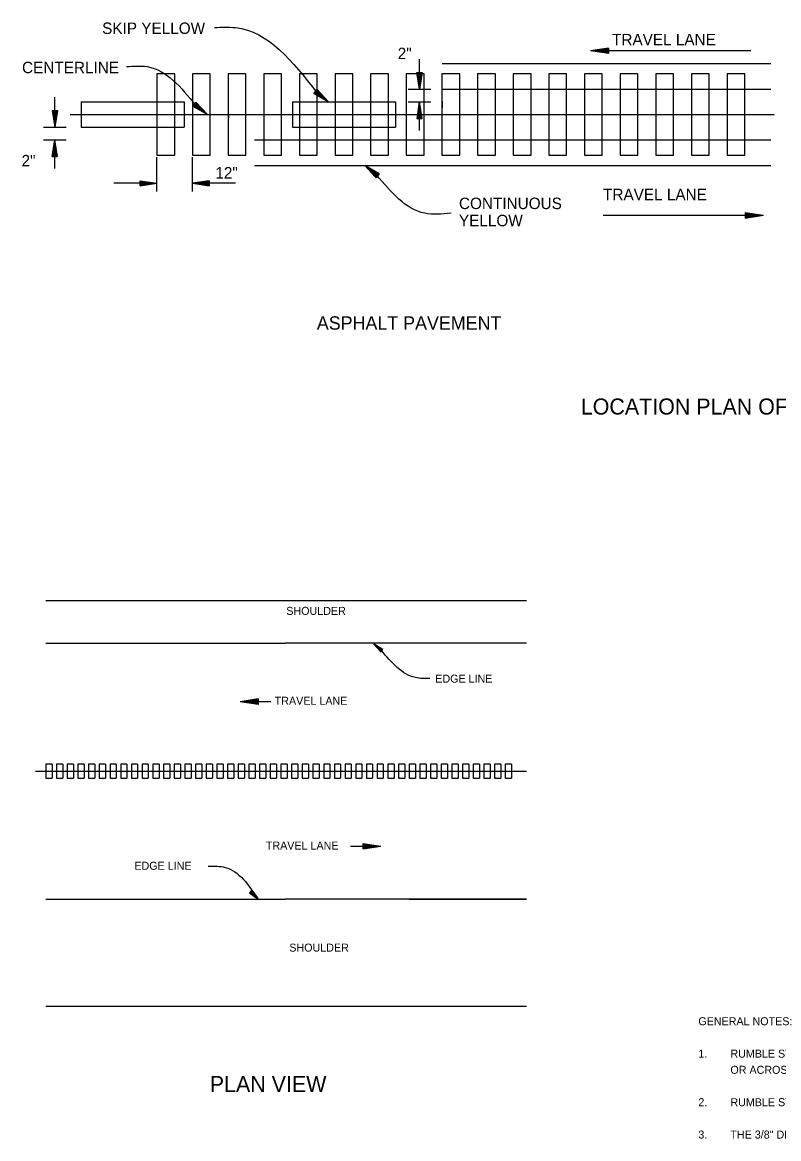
# Model space of a CAD drawing. Extents: x 28704 to 32542, y 50360 to 59122.
# Drawn here: x 31087 to 31666, y 50408 to 51264 of the extents above; entities that cross this region are included whole.
import ezdxf

# ---------------------------------------------------------------- set-up
doc = ezdxf.new("R2010")
doc.units = 0
doc.layers.add('Default', color=7, linetype='Continuous')
doc.layers.add('R_Alt Surface', color=7, linetype='Continuous')

msp = doc.modelspace()

# ---------------------------------------------------------------- linework, layer by layer
at = {"layer": 'Default'}
for p, q in [((31535.97, 51243.94), (31522, 51241.84)), ((31644.8, 51241.84), (31522, 51241.84)), ((31535.97, 51239.75), (31522, 51241.84)), ((31535.97, 51243.59), (31524.34, 51241.84)), ((31535.97, 51240.1), (31524.34, 51241.84)), ((31535.97, 51243.23), (31526.74, 51241.84)), ((31535.97, 51240.45), (31526.74, 51241.84)), ((31535.97, 51242.88), (31529.06, 51241.84)), ((31535.97, 51240.8), (31529.06, 51241.84)), ((31535.97, 51242.52), (31531.43, 51241.84)), ((31535.97, 51241.16), (31531.43, 51241.84)), ((31535.97, 51242.17), (31533.76, 51241.84)), ((31535.97, 51241.52), (31533.76, 51241.84)), ((31535.97, 51243.94), (31535.97, 51239.75)), ((31390.99, 51212.52), (31390.99, 51235.58)), ((31389.13, 51225.33), (31391.05, 51212.52)), ((31389.13, 51225.33), (31392.97, 51225.33)), ((31389.45, 51225.33), (31391.05, 51214.66)), ((31389.77, 51225.33), (31391.05, 51216.86)), ((31390.09, 51225.33), (31391.05, 51218.99)), ((31390.43, 51225.33), (31391.05, 51221.16)), ((31390.75, 51225.33), (31391.05, 51223.3)), ((31392.97, 51225.33), (31391.05, 51212.52)), ((31391.68, 51225.33), (31391.05, 51221.16)), ((31392.32, 51225.33), (31391.05, 51216.86)), ((31392.65, 51225.33), (31391.05, 51214.66)), ((31392, 51225.33), (31391.05, 51218.99)), ((31391.35, 51225.33), (31391.05, 51223.3)), ((31111.49, 51183.26), (31111.49, 51206.32)), ((31310.09, 51209.25), (31312.48, 51212.26)), ((31310.09, 51209.25), (31321.3, 51202.77)), ((31310.29, 51209.5), (31319.62, 51204.1)), ((31310.49, 51209.76), (31317.9, 51205.47)), ((31310.69, 51210.01), (31316.24, 51206.8)), ((31310.9, 51210.27), (31314.54, 51208.16)), ((31311.1, 51210.52), (31312.87, 51209.49)), ((31311.47, 51210.99), (31312.87, 51209.49)), ((31311.68, 51211.25), (31314.54, 51208.16)), ((31311.88, 51211.5), (31316.24, 51206.8)), ((31312.08, 51211.75), (31317.9, 51205.47)), ((31312.28, 51212.01), (31319.62, 51204.1)), ((31312.48, 51212.26), (31321.3, 51202.77)), ((31382.3, 51212.52), (31399.8, 51212.52)), ((31109.63, 51196.07), (31111.55, 51183.26)), ((31109.63, 51196.07), (31113.47, 51196.07)), ((31109.95, 51196.07), (31111.55, 51185.4)), ((31110.28, 51196.07), (31111.55, 51187.6)), ((31110.6, 51196.07), (31111.55, 51189.74)), ((31110.93, 51196.07), (31111.55, 51191.9)), ((31111.25, 51196.07), (31111.55, 51194.04)), ((31113.47, 51196.07), (31111.55, 51183.26)), ((31112.18, 51196.07), (31111.55, 51191.9)), ((31112.83, 51196.07), (31111.55, 51187.6)), ((31113.15, 51196.07), (31111.55, 51185.4)), ((31112.5, 51196.07), (31111.55, 51189.74)), ((31111.85, 51196.07), (31111.55, 51194.04)), ((31217.24, 51199.5), (31219.64, 51202.5)), ((31217.24, 51199.5), (31228.45, 51193.02)), ((31217.44, 51199.75), (31226.78, 51194.35)), ((31217.64, 51200), (31225.06, 51195.72)), ((31217.84, 51200.26), (31223.39, 51197.05)), ((31218.05, 51200.52), (31221.69, 51198.4)), ((31218.25, 51200.77), (31220.02, 51199.74)), ((31218.63, 51201.24), (31220.02, 51199.74)), ((31218.83, 51201.49), (31221.69, 51198.4)), ((31219.03, 51201.75), (31223.39, 51197.05)), ((31219.23, 51202), (31225.06, 51195.72)), ((31219.44, 51202.25), (31226.78, 51194.35)), ((31219.64, 51202.5), (31228.45, 51193.02)), ((31382.3, 51202.77), (31399.8, 51202.77)), ((31389.13, 51189.96), (31391.05, 51202.77)), ((31389.45, 51189.96), (31391.05, 51200.63)), ((31389.78, 51189.96), (31391.05, 51198.43)), ((31390.1, 51189.96), (31391.05, 51196.3)), ((31392.97, 51189.96), (31391.05, 51202.77)), ((31392.65, 51189.96), (31391.05, 51200.63)), ((31392.32, 51189.96), (31391.05, 51198.43)), ((31392, 51189.96), (31391.05, 51196.3)), ((31123.41, 51193.02), (31662.88, 51193.02)), ((31392.97, 51189.96), (31389.13, 51189.96)), ((31390.42, 51189.96), (31391.05, 51194.13)), ((31390.75, 51189.96), (31391.05, 51191.99)), ((31390.99, 51180.83), (31390.99, 51189.96)), ((31391.67, 51189.96), (31391.05, 51194.13)), ((31391.35, 51189.96), (31391.05, 51191.99)), ((31102.8, 51183.26), (31120.3, 51183.26)), ((31102.8, 51173.51), (31120.3, 51173.51)), ((31109.63, 51160.7), (31111.55, 51173.51)), ((31109.95, 51160.7), (31111.55, 51171.37)), ((31113.47, 51160.7), (31111.55, 51173.51)), ((31113.15, 51160.7), (31111.55, 51171.37)), ((31110.28, 51160.7), (31111.55, 51169.17)), ((31110.6, 51160.7), (31111.55, 51167.04)), ((31110.92, 51160.7), (31111.55, 51164.87)), ((31111.25, 51160.7), (31111.55, 51162.73)), ((31112.83, 51160.7), (31111.55, 51169.17)), ((31112.51, 51160.7), (31111.55, 51167.04)), ((31112.17, 51160.7), (31111.55, 51164.87)), ((31111.85, 51160.7), (31111.55, 51162.73)), ((31113.47, 51160.7), (31109.63, 51160.7)), ((31111.49, 51151.57), (31111.49, 51160.7)), ((31189.74, 51133.93), (31189.74, 51160.2)), ((31216.99, 51133.89), (31216.99, 51160.26)), ((31360.2, 51147.5), (31349, 51154)), ((31357.8, 51144.5), (31349, 51154)), ((31360, 51147.25), (31350.67, 51152.67)), ((31358, 51144.75), (31350.67, 51152.67)), ((31358.2, 51145.01), (31352.39, 51151.29)), ((31359.8, 51147), (31352.39, 51151.29)), ((31359.6, 51146.75), (31354.06, 51149.96)), ((31358.41, 51145.26), (31354.06, 51149.96)), ((31358.61, 51145.51), (31355.75, 51148.6)), ((31359.39, 51146.49), (31355.75, 51148.6)), ((31358.81, 51145.77), (31357.42, 51147.27)), ((31359.19, 51146.24), (31357.42, 51147.27)), ((31360.2, 51147.5), (31357.8, 51144.5)), ((31176.93, 51140.32), (31156.84, 51140.32)), ((31176.92, 51142.24), (31189.74, 51140.38)), ((31176.94, 51138.4), (31176.92, 51142.24)), ((31176.93, 51141.92), (31187.6, 51140.37)), ((31176.93, 51141.59), (31185.4, 51140.36)), ((31176.93, 51141.27), (31183.27, 51140.35)), ((31176.93, 51140.95), (31181.1, 51140.34)), ((31176.93, 51140.62), (31178.96, 51140.33)), ((31176.93, 51140.02), (31178.96, 51140.33)), ((31176.94, 51138.4), (31189.74, 51140.38)), ((31176.94, 51138.72), (31187.6, 51140.37)), ((31176.94, 51139.05), (31185.4, 51140.36)), ((31176.94, 51139.37), (31183.27, 51140.35)), ((31176.94, 51139.7), (31181.1, 51140.34)), ((31229.81, 51142.21), (31216.99, 51140.34)), ((31229.79, 51138.37), (31216.99, 51140.34)), ((31229.8, 51141.89), (31219.13, 51140.33)), ((31229.79, 51138.69), (31219.13, 51140.33)), ((31229.8, 51141.56), (31221.33, 51140.32)), ((31229.79, 51139.01), (31221.33, 51140.32)), ((31229.8, 51141.24), (31223.46, 51140.32)), ((31229.79, 51139.33), (31223.46, 51140.32)), ((31229.8, 51140.91), (31225.63, 51140.31)), ((31229.79, 51139.66), (31225.63, 51140.31)), ((31229.8, 51140.59), (31227.77, 51140.3)), ((31229.8, 51139.99), (31227.77, 51140.3)), ((31229.81, 51142.21), (31229.79, 51138.37)), ((31249.89, 51140.29), (31229.8, 51140.29)), ((31531.78, 51115.7), (31654.58, 51115.7)), ((31640.61, 51117.79), (31654.58, 51115.7)), ((31640.61, 51117.79), (31640.61, 51113.6)), ((31640.61, 51117.44), (31652.25, 51115.7)), ((31640.61, 51117.09), (31649.85, 51115.7)), ((31640.61, 51116.74), (31647.52, 51115.7)), ((31640.61, 51116.37), (31645.15, 51115.7)), ((31640.61, 51116.02), (31642.82, 51115.7)), ((31640.61, 51113.6), (31654.58, 51115.7)), ((31640.61, 51115.01), (31645.15, 51115.7)), ((31640.61, 51114.31), (31649.85, 51115.7)), ((31640.61, 51113.95), (31652.25, 51115.7)), ((31640.61, 51114.66), (31647.52, 51115.7)), ((31640.61, 51115.37), (31642.82, 51115.7))]:
    msp.add_line(p, q, dxfattribs=at)
for points in [[(31189.74, 51224.21), (31189.74, 51161.82), (31203.39, 51161.82), (31203.39, 51224.21)], [(31217.05, 51224.21), (31217.05, 51161.82), (31230.7, 51161.82), (31230.7, 51224.21)], [(31244.35, 51224.21), (31244.35, 51161.82), (31258.01, 51161.82), (31258.01, 51224.21)], [(31271.66, 51224.21), (31271.66, 51161.82), (31285.31, 51161.82), (31285.31, 51224.21)], [(31298.97, 51224.21), (31298.97, 51161.82), (31312.62, 51161.82), (31312.62, 51224.21)], [(31326.28, 51224.21), (31326.28, 51161.82), (31339.93, 51161.82), (31339.93, 51224.21)], [(31353.58, 51224.21), (31353.58, 51161.82), (31367.24, 51161.82), (31367.24, 51224.21)], [(31380.89, 51224.21), (31380.89, 51161.82), (31394.54, 51161.82), (31394.54, 51224.21)], [(31408.2, 51224.21), (31408.2, 51161.82), (31421.85, 51161.82), (31421.85, 51224.21)], [(31435.51, 51224.21), (31435.51, 51161.82), (31449.16, 51161.82), (31449.16, 51224.21)], [(31462.81, 51224.21), (31462.81, 51161.82), (31476.47, 51161.82), (31476.47, 51224.21)], [(31490.12, 51224.21), (31490.12, 51161.82), (31503.77, 51161.82), (31503.77, 51224.21)], [(31517.43, 51224.21), (31517.43, 51161.82), (31531.08, 51161.82), (31531.08, 51224.21)], [(31544.73, 51224.21), (31544.73, 51161.82), (31558.39, 51161.82), (31558.39, 51224.21)], [(31572.04, 51224.21), (31572.04, 51161.82), (31585.7, 51161.82), (31585.7, 51224.21)], [(31599.35, 51224.21), (31599.35, 51161.82), (31613, 51161.82), (31613, 51224.21)], [(31626.66, 51224.21), (31626.66, 51161.82), (31640.31, 51161.82), (31640.31, 51224.21)]]:
    msp.add_lwpolyline(points, close=True, dxfattribs=at)
for points in [[(31233.81, 51259.69), (31249.89, 51259.69), (31312.16, 51210.08)], [(31166.5, 51229.74), (31182.39, 51229.74), (31219.31, 51200.32)], [(31415.17, 51117.28), (31395.06, 51117.28), (31358.14, 51146.69)]]:
    msp.add_spline(points, degree=3, dxfattribs=at)
at = {"layer": 'R_Alt Surface'}
for p, q in [((31408.33, 51232.03), (31660.31, 51232.03)), ((31408.33, 51212.52), (31660.31, 51212.52)), ((31131.85, 51202.77), (31131.85, 51183.26)), ((31131.85, 51202.77), (31210.62, 51202.77)), ((31210.62, 51202.77), (31210.62, 51183.26)), ((31293.78, 51202.77), (31293.78, 51183.26)), ((31293.78, 51202.77), (31372.56, 51202.77)), ((31372.56, 51202.77), (31372.56, 51183.26)), ((31408.33, 51203.25), (31408.33, 51198.13)), ((31244.65, 51193.02), (31244.65, 51190.46)), ((31131.85, 51183.26), (31210.62, 51183.26)), ((31293.78, 51183.26), (31372.56, 51183.26)), ((31264.63, 51173.51), (31660.31, 51173.51)), ((31264.63, 51154), (31660.31, 51154)), ((31104.72, 50820.36), (31472.99, 50820.36)), ((31104.72, 50787.62), (31287.99, 50787.62)), ((31472.99, 50787.62), (31287.99, 50787.62)), ((31361.39, 50780.91), (31355.76, 50786.98)), ((31362.92, 50782.83), (31355.76, 50786.98)), ((31361.51, 50781.07), (31356.82, 50786.13)), ((31362.8, 50782.67), (31356.82, 50786.13)), ((31362.65, 50782.5), (31357.93, 50785.27)), ((31361.65, 50781.23), (31357.93, 50785.27)), ((31361.77, 50781.4), (31358.99, 50784.41)), ((31362.53, 50782.34), (31358.99, 50784.41)), ((31362.39, 50782.18), (31360.08, 50783.53)), ((31361.9, 50781.56), (31360.08, 50783.53)), ((31362.27, 50782.01), (31361.14, 50782.69)), ((31362.02, 50781.73), (31361.14, 50782.69)), ((31361.39, 50780.91), (31362.92, 50782.83)), ((31267.45, 50744.78), (31253.69, 50742.71)), ((31277.11, 50742.71), (31253.69, 50742.71)), ((31267.45, 50740.67), (31253.69, 50742.71)), ((31267.45, 50744.43), (31255.99, 50742.71)), ((31267.45, 50741), (31255.99, 50742.71)), ((31267.45, 50744.11), (31258.34, 50742.71)), ((31267.45, 50741.36), (31258.34, 50742.71)), ((31267.45, 50743.74), (31260.61, 50742.71)), ((31267.45, 50741.69), (31260.61, 50742.71)), ((31267.45, 50743.37), (31262.97, 50742.71)), ((31267.45, 50742.04), (31262.97, 50742.71)), ((31267.45, 50743.06), (31265.26, 50742.71)), ((31267.45, 50742.39), (31265.26, 50742.71)), ((31267.45, 50744.78), (31267.45, 50740.67)), ((31109.51, 50694.83), (31104.72, 50694.83)), ((31104.72, 50694.83), (31104.72, 50683.94)), ((31109.51, 50694.83), (31109.51, 50683.94)), ((31117.7, 50694.83), (31112.91, 50694.83)), ((31112.91, 50694.83), (31112.91, 50683.94)), ((31117.7, 50694.83), (31117.7, 50683.94)), ((31125.88, 50694.83), (31121.1, 50694.83)), ((31121.1, 50694.83), (31121.1, 50683.94)), ((31125.88, 50694.83), (31125.88, 50683.94)), ((31134.07, 50694.83), (31129.28, 50694.83)), ((31129.28, 50694.83), (31129.28, 50683.94)), ((31134.07, 50694.83), (31134.07, 50683.94)), ((31142.26, 50694.83), (31137.47, 50694.83)), ((31137.47, 50694.83), (31137.47, 50683.94)), ((31142.26, 50694.83), (31142.26, 50683.94)), ((31150.44, 50694.83), (31145.65, 50694.83)), ((31145.65, 50694.83), (31145.65, 50683.94)), ((31150.44, 50694.83), (31150.44, 50683.94)), ((31158.63, 50694.83), (31153.84, 50694.83)), ((31153.84, 50694.83), (31153.84, 50683.94)), ((31158.63, 50694.83), (31158.63, 50683.94)), ((31166.82, 50694.83), (31162.03, 50694.83)), ((31162.03, 50694.83), (31162.03, 50683.94)), ((31166.82, 50694.83), (31166.82, 50683.94)), ((31175, 50694.83), (31170.21, 50694.83)), ((31170.21, 50694.83), (31170.21, 50683.94)), ((31175, 50694.83), (31175, 50683.94)), ((31183.19, 50694.83), (31178.4, 50694.83)), ((31178.4, 50694.83), (31178.4, 50683.94)), ((31183.19, 50694.83), (31183.19, 50683.94)), ((31191.38, 50694.83), (31186.59, 50694.83)), ((31186.59, 50694.83), (31186.59, 50683.94)), ((31191.38, 50694.83), (31191.38, 50683.94)), ((31199.56, 50694.83), (31194.77, 50694.83)), ((31194.77, 50694.83), (31194.77, 50683.94)), ((31199.56, 50694.83), (31199.56, 50683.94)), ((31207.75, 50694.83), (31202.96, 50694.83)), ((31202.96, 50694.83), (31202.96, 50683.94)), ((31207.75, 50694.83), (31207.75, 50683.94)), ((31215.93, 50694.83), (31211.15, 50694.83)), ((31211.15, 50694.83), (31211.15, 50683.94)), ((31215.93, 50694.83), (31215.93, 50683.94)), ((31224.12, 50694.83), (31219.33, 50694.83)), ((31219.33, 50694.83), (31219.33, 50683.94)), ((31224.12, 50694.83), (31224.12, 50683.94)), ((31232.31, 50694.83), (31227.52, 50694.83)), ((31227.52, 50694.83), (31227.52, 50683.94)), ((31232.31, 50694.83), (31232.31, 50683.94)), ((31240.49, 50694.83), (31235.7, 50694.83)), ((31235.7, 50694.83), (31235.7, 50683.94)), ((31240.49, 50694.83), (31240.49, 50683.94)), ((31248.68, 50694.83), (31243.89, 50694.83)), ((31243.89, 50694.83), (31243.89, 50683.94)), ((31248.68, 50694.83), (31248.68, 50683.94)), ((31256.87, 50694.83), (31252.08, 50694.83)), ((31252.08, 50694.83), (31252.08, 50683.94)), ((31256.87, 50694.83), (31256.87, 50683.94)), ((31265.05, 50694.83), (31260.26, 50694.83)), ((31260.26, 50694.83), (31260.26, 50683.94)), ((31265.05, 50694.83), (31265.05, 50683.94)), ((31273.24, 50694.83), (31268.45, 50694.83)), ((31268.45, 50694.83), (31268.45, 50683.94)), ((31273.24, 50694.83), (31273.24, 50683.94)), ((31281.43, 50694.83), (31276.64, 50694.83)), ((31276.64, 50694.83), (31276.64, 50683.94)), ((31281.43, 50694.83), (31281.43, 50683.94)), ((31289.61, 50694.83), (31284.82, 50694.83)), ((31284.82, 50694.83), (31284.82, 50683.94)), ((31289.61, 50694.83), (31289.61, 50683.94)), ((31297.8, 50694.83), (31293.01, 50694.83)), ((31293.01, 50694.83), (31293.01, 50683.94)), ((31297.8, 50694.83), (31297.8, 50683.94)), ((31305.98, 50694.83), (31301.2, 50694.83)), ((31301.2, 50694.83), (31301.2, 50683.94)), ((31305.98, 50694.83), (31305.98, 50683.94)), ((31314.17, 50694.83), (31309.38, 50694.83)), ((31309.38, 50694.83), (31309.38, 50683.94)), ((31314.17, 50694.83), (31314.17, 50683.94)), ((31322.36, 50694.83), (31317.57, 50694.83)), ((31317.57, 50694.83), (31317.57, 50683.94)), ((31322.36, 50694.83), (31322.36, 50683.94)), ((31330.54, 50694.83), (31325.75, 50694.83)), ((31325.75, 50694.83), (31325.75, 50683.94)), ((31330.54, 50694.83), (31330.54, 50683.94)), ((31338.73, 50694.83), (31333.94, 50694.83)), ((31333.94, 50694.83), (31333.94, 50683.94)), ((31338.73, 50694.83), (31338.73, 50683.94)), ((31346.92, 50694.83), (31342.13, 50694.83)), ((31342.13, 50694.83), (31342.13, 50683.94)), ((31346.92, 50694.83), (31346.92, 50683.94)), ((31355.1, 50694.83), (31350.31, 50694.83)), ((31350.31, 50694.83), (31350.31, 50683.94)), ((31355.1, 50694.83), (31355.1, 50683.94)), ((31363.29, 50694.83), (31358.5, 50694.83)), ((31358.5, 50694.83), (31358.5, 50683.94)), ((31363.29, 50694.83), (31363.29, 50683.94)), ((31371.48, 50694.83), (31366.69, 50694.83)), ((31366.69, 50694.83), (31366.69, 50683.94)), ((31371.48, 50694.83), (31371.48, 50683.94)), ((31379.66, 50694.83), (31374.87, 50694.83)), ((31374.87, 50694.83), (31374.87, 50683.94)), ((31379.66, 50694.83), (31379.66, 50683.94)), ((31387.85, 50694.83), (31383.06, 50694.83)), ((31383.06, 50694.83), (31383.06, 50683.94)), ((31387.85, 50694.83), (31387.85, 50683.94)), ((31396.03, 50694.83), (31391.25, 50694.83)), ((31391.25, 50694.83), (31391.25, 50683.94)), ((31396.03, 50694.83), (31396.03, 50683.94)), ((31404.22, 50694.83), (31399.43, 50694.83)), ((31399.43, 50694.83), (31399.43, 50683.94)), ((31404.22, 50694.83), (31404.22, 50683.94)), ((31412.41, 50694.83), (31407.62, 50694.83)), ((31407.62, 50694.83), (31407.62, 50683.94)), ((31412.41, 50694.83), (31412.41, 50683.94)), ((31420.59, 50694.83), (31415.8, 50694.83)), ((31415.8, 50694.83), (31415.8, 50683.94)), ((31420.59, 50694.83), (31420.59, 50683.94)), ((31428.78, 50694.83), (31423.99, 50694.83)), ((31423.99, 50694.83), (31423.99, 50683.94)), ((31428.78, 50694.83), (31428.78, 50683.94)), ((31436.97, 50694.83), (31432.18, 50694.83)), ((31432.18, 50694.83), (31432.18, 50683.94)), ((31436.97, 50694.83), (31436.97, 50683.94)), ((31445.15, 50694.83), (31440.36, 50694.83)), ((31440.36, 50694.83), (31440.36, 50683.94)), ((31445.15, 50694.83), (31445.15, 50683.94)), ((31453.34, 50694.83), (31448.55, 50694.83)), ((31448.55, 50694.83), (31448.55, 50683.94)), ((31453.34, 50694.83), (31453.34, 50683.94)), ((31461.53, 50694.83), (31456.74, 50694.83)), ((31456.74, 50694.83), (31456.74, 50683.94)), ((31461.53, 50694.83), (31461.53, 50683.94)), ((31096.62, 50689.38), (31472.99, 50689.38)), ((31104.72, 50683.94), (31109.51, 50683.94)), ((31112.91, 50683.94), (31117.7, 50683.94)), ((31121.1, 50683.94), (31125.88, 50683.94)), ((31129.28, 50683.94), (31134.07, 50683.94)), ((31137.47, 50683.94), (31142.26, 50683.94)), ((31145.65, 50683.94), (31150.44, 50683.94)), ((31153.84, 50683.94), (31158.63, 50683.94)), ((31162.03, 50683.94), (31166.82, 50683.94)), ((31170.21, 50683.94), (31175, 50683.94)), ((31178.4, 50683.94), (31183.19, 50683.94)), ((31186.59, 50683.94), (31191.38, 50683.94)), ((31194.77, 50683.94), (31199.56, 50683.94)), ((31202.96, 50683.94), (31207.75, 50683.94)), ((31211.15, 50683.94), (31215.93, 50683.94)), ((31219.33, 50683.94), (31224.12, 50683.94)), ((31227.52, 50683.94), (31232.31, 50683.94)), ((31235.7, 50683.94), (31240.49, 50683.94)), ((31243.89, 50683.94), (31248.68, 50683.94)), ((31252.08, 50683.94), (31256.87, 50683.94)), ((31260.26, 50683.94), (31265.05, 50683.94)), ((31268.45, 50683.94), (31273.24, 50683.94)), ((31276.64, 50683.94), (31281.43, 50683.94)), ((31284.82, 50683.94), (31289.61, 50683.94)), ((31293.01, 50683.94), (31297.8, 50683.94)), ((31301.2, 50683.94), (31305.98, 50683.94)), ((31309.38, 50683.94), (31314.17, 50683.94)), ((31317.57, 50683.94), (31322.36, 50683.94)), ((31325.75, 50683.94), (31330.54, 50683.94)), ((31333.94, 50683.94), (31338.73, 50683.94)), ((31342.13, 50683.94), (31346.92, 50683.94)), ((31350.31, 50683.94), (31355.1, 50683.94)), ((31358.5, 50683.94), (31363.29, 50683.94)), ((31366.69, 50683.94), (31371.48, 50683.94)), ((31374.87, 50683.94), (31379.66, 50683.94)), ((31383.06, 50683.94), (31387.85, 50683.94)), ((31391.25, 50683.94), (31396.03, 50683.94)), ((31399.43, 50683.94), (31404.22, 50683.94)), ((31407.62, 50683.94), (31412.41, 50683.94)), ((31415.8, 50683.94), (31420.59, 50683.94)), ((31423.99, 50683.94), (31428.78, 50683.94)), ((31432.18, 50683.94), (31436.97, 50683.94)), ((31440.36, 50683.94), (31445.15, 50683.94)), ((31448.55, 50683.94), (31453.34, 50683.94)), ((31456.74, 50683.94), (31461.53, 50683.94)), ((31338.07, 50631.89), (31361.49, 50631.89)), ((31347.73, 50633.92), (31361.49, 50631.89)), ((31347.73, 50629.83), (31347.73, 50633.92)), ((31347.73, 50633.59), (31359.2, 50631.89)), ((31347.73, 50633.25), (31356.84, 50631.89)), ((31347.73, 50632.9), (31354.57, 50631.89)), ((31347.73, 50632.55), (31352.22, 50631.89)), ((31347.73, 50632.22), (31349.92, 50631.89)), ((31347.73, 50629.83), (31361.49, 50631.89)), ((31347.73, 50631.22), (31352.22, 50631.89)), ((31347.73, 50630.5), (31356.84, 50631.89)), ((31347.73, 50630.15), (31359.2, 50631.89)), ((31347.73, 50630.85), (31354.57, 50631.89)), ((31347.73, 50631.55), (31349.92, 50631.89)), ((31262.31, 50597.8), (31260.61, 50596.04)), ((31261.33, 50596.77), (31262.39, 50596.02)), ((31261.59, 50597.04), (31262.39, 50596.02)), ((31261.74, 50597.18), (31263.37, 50595.06)), ((31261.88, 50597.35), (31264.38, 50594.09)), ((31262.02, 50597.49), (31265.34, 50593.15)), ((31262.17, 50597.63), (31266.36, 50592.17)), ((31262.31, 50597.8), (31267.34, 50591.21)), ((31104.72, 50591.15), (31287.99, 50591.15)), ((31260.61, 50596.04), (31267.34, 50591.21)), ((31260.75, 50596.18), (31266.36, 50592.17)), ((31260.9, 50596.32), (31265.34, 50593.15)), ((31261.04, 50596.47), (31264.38, 50594.09)), ((31261.18, 50596.61), (31263.37, 50595.06)), ((31472.99, 50591.15), (31287.99, 50591.15)), ((31383.06, 50591.15), (31472.99, 50591.15)), ((31104.72, 50509.28), (31472.99, 50509.28))]:
    msp.add_line(p, q, dxfattribs=at)
for points in [[(31389.06, 51225.33), (31392.92, 51225.33), (31391.05, 51212.52)], [(31389.06, 51189.96), (31392.92, 51189.96), (31391.05, 51202.77)], [(31109.56, 51160.7), (31113.42, 51160.7), (31111.55, 51173.51)], [(31359.23, 51148.07), (31357.04, 51145.32), (31349, 51154)], [(31176.93, 51138.39), (31176.93, 51142.25), (31189.74, 51140.38)], [(31229.8, 51138.36), (31229.8, 51142.22), (31216.99, 51140.34)]]:
    msp.add_lwpolyline(points, close=True, dxfattribs=at)
for points in [[(31399.02, 50760.38), (31387.93, 50761.18), (31361.86, 50781.95)], [(31229.07, 50616.54), (31242.11, 50615.64), (31267.34, 50591.21)]]:
    msp.add_spline(points, degree=3, dxfattribs=at)

# ---------------------------------------------------------------- texts
at = {"layer": 'Default'}
for s, height, p in [('SKIP YELLOW', 8.7711, (31147.82, 51254.81)), ('TRAVEL LANE', 8.7711, (31538.57, 51246.1)), ('2"', 8.771, (31374.33, 51235.5)), ('CENTERLINE', 8.771, (31086.43, 51224.71)), ('2"', 8.771, (31086.06, 51153.27)), ('12"', 8.771, (31234.56, 51143.94)), ('TRAVEL LANE', 8.7711, (31531.69, 51127.32)), ('CONTINUOUS ', 8.7711, (31421.26, 51120.49)), ('YELLOW', 8.771, (31421.26, 51107.34)), ('ASPHALT PAVEMENT', 10.2329, (31312.34, 51028.02))]:
    msp.add_text(s, height=height, dxfattribs=at).set_placement(p)
at = {"layer": 'R_Alt Surface'}
for s, height, p in [('LOCATION PLAN OF CENTERLINE RUMBLE STRIPES', 12.2795, (31514.6, 50962.95)), ('SHOULDER', 6.14, (31288.92, 50809.29)), ('EDGE LINE', 6.14, (31403.09, 50757.29)), ('TRAVEL LANE', 6.1398, (31280.06, 50740.34)), ('TRAVEL LANE', 6.1398, (31273.27, 50629.34)), ('EDGE LINE', 6.14, (31172.5, 50613.81)), ('SHOULDER', 6.14, (31291.25, 50551.05)), ('GENERAL NOTES:', 6.1398, (31604.7, 50494.57)), ('1.', 6.14, (31604.7, 50469.74)), ('RUMBLE STRIPES SHALL NOT BE INSTALLED ON BRIDGE DECKS, APPROACH SLABS, INTERSECTING STREETS OR ROADWAYS,', 6.13977, (31629.26, 50469.74)), ('OR ACROSS TRANSVERSE JOINTS OF CONCRETE SHOULDERS.', 6.1398, (31629.26, 50457.33)), ('PLAN VIEW ', 12.28, (31230.27, 50443.39)), ('2.', 6.14, (31604.7, 50432.51)), ('RUMBLE STRIPES SHALL BE MEASURED BY THE LINEAR FOOT LONGITUDINALLY ALONG THE CENTERLINE.', 6.1398, (31629.26, 50432.51)), ('3.', 6.14, (31604.7, 50407.68)), ('THE 3/8" DEPTH SHALL GENERALLY APPLY FOR THE ENTIRE 16" LENGTH.  SOME VARIATION TO SUIT SLOPE BREAKS MAY BE NECESSARY.', 6.13977, (31629.26, 50407.68))]:
    msp.add_text(s, height=height, dxfattribs=at).set_placement(p)

doc.saveas('drawing.dxf')
